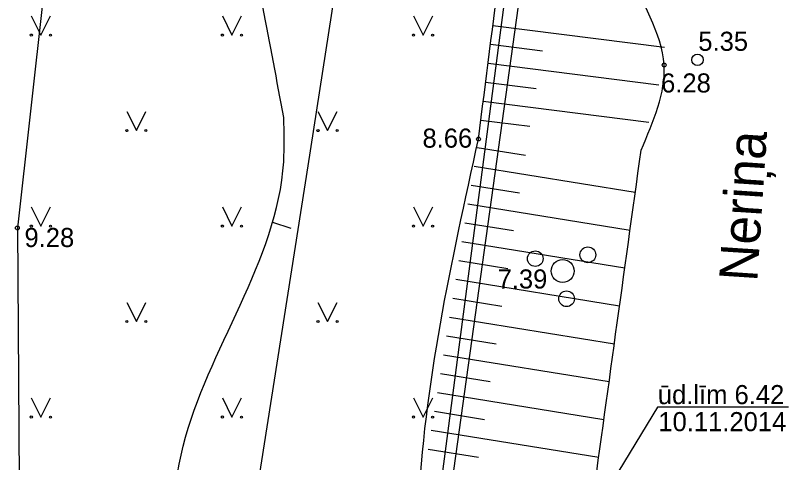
# Model space of a CAD drawing. Extents: x 496127 to 496334, y 303823 to 303967.
# Drawn here: x 496199.34 to 496219.56, y 303903.81 to 303915.51 of the extents above; entities that cross this region are included whole.
import ezdxf

# ---------------------------------------------------------------- set-up
doc = ezdxf.new("R2010")
doc.units = 0
for name, color, linetype in [('APGR_AIZS_####_####_#', 7, 'Continuous'), ('HIDG_AATZ_####_TKST_#', 7, 'Continuous'), ('HIDG_ELEM_####_####_#', 7, 'Continuous'), ('HIDG_HNOS_####_TKST_#', 7, 'Continuous'), ('HIDG_PLIN_####_####_#', 7, 'Continuous'), ('HIDG_UATZ_####_TKST_#', 7, 'Continuous'), ('Level 24', 7, 'Continuous'), ('RAMI_UZMR_####_####_#', 7, 'Continuous'), ('RELJ_AATZ_####_TKST_#', 7, 'Continuous'), ('RELJ_ELEM_####_####_#', 7, 'Continuous'), ('RELJ_HORZ_PAMT_####_#', 7, 'Continuous'), ('RELJ_NOGA_####_####_#', 7, 'Continuous'), ('SAKT_VADP_KABE_####_#', 7, 'Continuous'), ('TERT_ELEM_####_####_#', 7, 'Continuous')]:
    doc.layers.add(name, color=color, linetype=linetype)

msp = doc.modelspace()

# ---------------------------------------------------------------- linework, layer by layer
at = {"layer": 'APGR_AIZS_####_####_#'}
msp.add_lwpolyline([(496206.4995346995, 303871.05611915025), (496206.335, 303871.77), (496213.9347901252, 303929.61474146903)], dxfattribs=at)
at = {"layer": 'HIDG_ELEM_####_####_#'}
msp.add_circle((496217.178, 303914.352), 0.15, dxfattribs=at)
at = {"layer": 'HIDG_PLIN_####_####_#'}
for points in [[(496215.70300000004, 303911.989), (496216.304, 303914.216), (496215.397, 303916.759), (496216.05500000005, 303921.1770000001), (496217.113, 303922.543), (496217.201, 303926.345), (496218.123, 303932.8670000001)], [(496214.371023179, 303902.34320098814), (496214.375, 303902.372), (496215.03701158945, 303907.16610049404), (496215.70300000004, 303911.989)]]:
    msp.add_spline(points, degree=3, dxfattribs=at)
at = {"layer": 'HIDG_UATZ_####_TKST_#'}
msp.add_lwpolyline([(496219.5593709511, 303905.2604011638), (496216.13300517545, 303905.2604011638), (496214.375, 303902.372)], dxfattribs=at)
at = {"layer": 'Level 24'}
msp.add_lwpolyline([(496207.01700000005, 303876.3870000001), (496214.9720000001, 303933.58599999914)], dxfattribs=at)
at = {"layer": 'RAMI_UZMR_####_####_#'}
for p, q in [((496201.94004930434, 303932.85977279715), (496199.38609252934, 303909.9507435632)), ((496199.38609252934, 303909.9507435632), (496199.7497200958, 303859.99954969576))]:
    msp.add_line(p, q, dxfattribs=at)
at = {"layer": 'RELJ_ELEM_####_####_#'}
for centre in [(496216.304, 303914.216), (496211.44800000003, 303912.278), (496199.38609252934, 303909.9507435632)]:
    msp.add_circle(centre, 0.05, dxfattribs=at)
at = {"layer": 'RELJ_HORZ_PAMT_####_#'}
msp.add_line((496206.5475176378, 303909.9320581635), (496206.07302527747, 303910.0897191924), dxfattribs=at)
for points in [[(496206.35287790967, 303912.84153467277), (496205.14786512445, 303918.60282575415), (496201.36357086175, 303928.9642678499)], [(496203.43929208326, 303882.73108822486), (496203.1793277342, 303888.0777126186), (496203.72500604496, 303896.29673976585), (496203.72500604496, 303904.2417309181), (496206.35287790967, 303911.6848359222), (496206.35287790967, 303912.84153467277)]]:
    msp.add_spline(points, degree=3, dxfattribs=at)
at = {"layer": 'RELJ_NOGA_####_####_#'}
for p, q in [((496211.82463263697, 303915.2542640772), (496216.3151407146, 303914.68601077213)), ((496211.76186053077, 303914.7582200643), (496213.1219527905, 303914.5861065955)), ((496211.6990884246, 303914.26217605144), (496216.1639818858, 303913.69716415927)), ((496211.6363163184, 303913.76613203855), (496212.95516013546, 303913.599238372)), ((496211.5735442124, 303913.2700880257), (496215.9009428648, 303912.7224754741)), ((496211.5107721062, 303912.7740440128), (496212.7883674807, 303912.6123701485)), ((496211.44800000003, 303912.278), (496211.44899208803, 303912.2778744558)), ((496211.4127686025, 303912.06046790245), (496212.67457857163, 303911.8561057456)), ((496211.3328304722, 303911.5668993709), (496215.5503878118, 303910.883825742)), ((496211.25289234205, 303911.07333083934), (496212.5216167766, 303910.8678488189)), ((496211.1729542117, 303910.5797623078), (496215.41355976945, 303909.8929558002)), ((496211.09301608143, 303910.0861937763), (496212.36865498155, 303909.8795918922)), ((496211.01307795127, 303909.59262524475), (496215.2767317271, 303908.9020858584)), ((496210.933139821, 303909.09905671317), (496212.2156931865, 303908.8913349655)), ((496210.8532016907, 303908.60548818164), (496215.13990368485, 303907.9112159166)), ((496210.7732635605, 303908.1119196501), (496212.06273139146, 303907.90307803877)), ((496210.6933254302, 303907.6183511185), (496215.0030756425, 303906.92034597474)), ((496210.61338729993, 303907.124782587), (496211.9097695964, 303906.91482111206)), ((496210.5334491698, 303906.63121405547), (496214.8662476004, 303905.92947603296)), ((496210.4535110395, 303906.1376455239), (496211.7568078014, 303905.92656418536)), ((496210.3735729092, 303905.64407699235), (496214.7294195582, 303904.9386060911)), ((496210.293634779, 303905.1505084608), (496211.60384600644, 303904.93830725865)), ((496210.2136966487, 303904.65693992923), (496214.59259151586, 303903.9477361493)), ((496210.13375851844, 303904.1633713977), (496211.4508842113, 303903.9500503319))]:
    msp.add_line(p, q, dxfattribs=at)
for points in [[(496211.44800000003, 303912.278), (496212.609, 303921.456), (496214.059, 303932.95300000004)], [(496210.0189999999, 303900.70499999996), (496210.03968502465, 303900.8194401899), (496210.0494270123, 303900.9340895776), (496210.0420404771, 303901.1638720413), (496209.96149556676, 303901.62436438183), (496209.8727028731, 303902.08417453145), (496209.87100000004, 303902.5410000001), (496211.44800000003, 303912.278)]]:
    msp.add_spline(points, degree=3, dxfattribs=at)
at = {"layer": 'SAKT_VADP_KABE_####_#'}
msp.add_lwpolyline([(496210.22441647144, 303932.50419576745), (496206.98339564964, 303911.5742437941), (496201.4415504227, 303876.2440306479), (496202.13331453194, 303859.82312708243)], dxfattribs=at)
at = {"layer": 'TERT_ELEM_####_####_#'}
for p, q in [((496199.75, 303915.5), (496200, 303915)), ((496200, 303915), (496200.25, 303915.5)), ((496204.75, 303915.5), (496205, 303915)), ((496205, 303915), (496205.25, 303915.5)), ((496209.75, 303915.5), (496210, 303915)), ((496210, 303915), (496210.25, 303915.5)), ((496202.25, 303913), (496202.5, 303912.5)), ((496202.5, 303912.5), (496202.75, 303913)), ((496207.25, 303913), (496207.5, 303912.5)), ((496207.5, 303912.5), (496207.75, 303913)), ((496199.75, 303910.5), (496200, 303910)), ((496200, 303910), (496200.25, 303910.5)), ((496204.75, 303910.5), (496205, 303910)), ((496205, 303910), (496205.25, 303910.5)), ((496209.75, 303910.5), (496210, 303910)), ((496210, 303910), (496210.25, 303910.5)), ((496202.25, 303908), (496202.5, 303907.5)), ((496202.5, 303907.5), (496202.75, 303908)), ((496207.25, 303908), (496207.5, 303907.5)), ((496207.5, 303907.5), (496207.75, 303908)), ((496199.75, 303905.5), (496200, 303905)), ((496200, 303905), (496200.25, 303905.5)), ((496204.75, 303905.5), (496205, 303905)), ((496205, 303905), (496205.25, 303905.5)), ((496209.75, 303905.5), (496210, 303905)), ((496210, 303905), (496210.25, 303905.5))]:
    msp.add_line(p, q, dxfattribs=at)
for centre, radius in [((496199.7497200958, 303914.99954969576), 0.02800000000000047), ((496200.2497200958, 303914.99954969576), 0.02630589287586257), ((496204.7497200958, 303914.99954969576), 0.02800000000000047), ((496205.2497200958, 303914.99954969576), 0.02630589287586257), ((496209.7497200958, 303914.99954969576), 0.02800000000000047), ((496210.2497200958, 303914.99954969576), 0.02630589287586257), ((496202.2497200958, 303912.49954969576), 0.02800000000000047), ((496202.7497200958, 303912.49954969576), 0.02630589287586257), ((496207.2497200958, 303912.49954969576), 0.02800000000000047), ((496207.7497200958, 303912.49954969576), 0.02630589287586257), ((496199.7497200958, 303909.99954969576), 0.02800000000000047), ((496200.2497200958, 303909.99954969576), 0.02630589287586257), ((496204.7497200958, 303909.99954969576), 0.02800000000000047), ((496205.2497200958, 303909.99954969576), 0.02630589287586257), ((496209.7497200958, 303909.99954969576), 0.02800000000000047), ((496210.2497200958, 303909.99954969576), 0.02630589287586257), ((496214.31048458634, 303909.2478487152), 0.2066127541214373), ((496212.93486157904, 303909.1468479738), 0.20413472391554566), ((496213.64900000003, 303908.823), 0.3006396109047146), ((496213.75229362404, 303908.0954505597), 0.20454262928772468), ((496202.2497200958, 303907.49954969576), 0.02800000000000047), ((496202.7497200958, 303907.49954969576), 0.02630589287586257), ((496207.2497200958, 303907.49954969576), 0.02800000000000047), ((496207.7497200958, 303907.49954969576), 0.02630589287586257), ((496199.7497200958, 303904.99954969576), 0.02800000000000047), ((496200.2497200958, 303904.99954969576), 0.02630589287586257), ((496204.7497200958, 303904.99954969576), 0.02800000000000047), ((496205.2497200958, 303904.99954969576), 0.02630589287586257), ((496209.7497200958, 303904.99954969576), 0.02800000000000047), ((496210.2497200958, 303904.99954969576), 0.02630589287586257)]:
    msp.add_circle(centre, radius, dxfattribs=at)

# ---------------------------------------------------------------- texts
at = {"layer": 'HIDG_AATZ_####_TKST_#'}
msp.add_text(' 5.35', height=0.5, dxfattribs=at).set_placement((496217.01314007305, 303914.5874058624))
at = {"layer": 'HIDG_HNOS_####_TKST_#'}
msp.add_text('Neriņa', height=1, rotation=86.25950832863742, dxfattribs=at).set_placement((496218.7388470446, 303908.52943027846))
at = {"layer": 'HIDG_UATZ_####_TKST_#'}
for s, p in [('ūd.līm 6.42', (496216.14026450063, 303905.3374072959)), ('10.11.2014', (496216.15367801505, 303904.629873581))]:
    msp.add_text(s, height=0.5, dxfattribs=at).set_placement(p)
at = {"layer": 'RELJ_AATZ_####_TKST_#'}
for s, p in [(' 6.28', (496216.0395372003, 303913.49647499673)), (' 8.66', (496209.7976794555, 303912.0522756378)), (' 9.28', (496199.38609252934, 303909.4507435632)), (' 7.39', (496211.76261039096, 303908.3649459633))]:
    msp.add_text(s, height=0.5, dxfattribs=at).set_placement(p)

doc.saveas('drawing.dxf')
